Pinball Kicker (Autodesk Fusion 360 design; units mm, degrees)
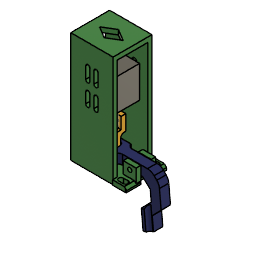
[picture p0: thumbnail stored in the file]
sketch "Solenoid Assy" plane through (0, 0, 0) normal (0, 0, 1) x axis (1, 0, 0)
  line L1 (18.001, -16.536) -> (18.0004, 16.543)
  line L2 (-17.999, -16.5011) -> (-17.9996, 16.5424)
  line L3 (-17.9995, 13.0183) -> (18.0005, 13.0189)
  line L4 (15.0006, -16.5331) -> (15, 16.543)
  line L5 (18.0004, 16.543) -> (-17.9996, 16.5424)
  line L6 (18.001, -16.536) -> (-17.999, -16.5011)
  line L7 (18, -12.9962) -> (-17.999, -12.999)
  line L8 (-14.9977, 16.5424) -> (-14.9977, 16.5374)
  line L9 (-17.999, -16.5011) -> (-17.999, -16.5011)
  line L10 (18.001, -12.9962) -> (18, -12.9962)
  line L11 (-14.9983, -16.504) -> (-14.9977, 16.5374)
  line L12 (-17.9995, -16.9987) -> (-17.999, -16.5011)
  line L13 (-17.9996, 16.5424) -> (-17.9993, 16.9967)
  line L14 (-15.5, -9.1) -> (-12.5, -9.1)
  line L15 (-15.5, -4.9) -> (-12.5, -4.9)
  line L16 (-15.5, 4.9) -> (-12.5, 4.9)
  line L17 (-15.5, 9.1) -> (-12.5, 9.1)
  arc A1 centre (-12.5, -7) radius 2.1 clockwise from (-12.5, -4.9) to (-12.5011, -9.1)
  arc A2 centre (-15.5, -7) radius 2.1 clockwise from (-15, -4.9604) to (-14.9981, -4.9609)
  arc A3 centre (-15.5, -7) radius 2.1 clockwise from (-15.4986, -9.1) to (-15.5, -4.9)
  arc A4 centre (-15.5, -7) radius 2.1 clockwise from (-14.9982, -9.0392) to (-15, -9.0396)
  arc A5 centre (-12.5, 7) radius 2.1 clockwise from (-12.5007, 9.1) to (-12.5, 4.9)
  arc A6 centre (-15.5, 7) radius 2.1 clockwise from (-15.5, 4.9) to (-15.4993, 9.1)
  arc A7 centre (-15.5, 7) radius 2.1 clockwise from (-14.9979, 4.9609) to (-15, 4.9604)
  arc A8 centre (-15.5, 7) radius 2.1 clockwise from (-15, 9.0396) to (-14.9979, 9.0391)
  point P13 (15.0006, -16.5331)
  point P12 (-14.9983, -16.504)
  point P10 (-17.999, -12.999)
  point P8 (-17.9995, 13.0183)
  point P4 (18.001, -12.9962)
  point P5 (-14.9977, 16.5424)
  point P15 (18.0005, 13.0189)
  point P16 (15, 16.543)
  point P23 (-12.5, -9.1)
  point P24 (-15.5, -9.1)
  point P26 (-15.5, -4.9)
  point P27 (-12.5011, -9.1)
  point P28 (-14.9982, -9.0392)
  point P29 (-14.9981, -4.9609)
  point P32 (-15.4986, -9.1)
  point P37 (-12.5, 9.1)
  point P38 (-15.5, 9.1)
  point P40 (-12.5007, 9.1)
  point P42 (-15.4993, 9.1)
  point P44 (-14.9979, 4.9609)
  point P45 (-14.9979, 9.0391)
  coincident P13 L6
  coincident P12 L6
  coincident P10 L2
  coincident P8 L2
  perpendicular L2 L9
  coincident P4 L1
  perpendicular L5 L8
  coincident P5 L5
  perpendicular L1 L3
  coincident L1 P15
  perpendicular L4 L5
  coincident L5 P16
  perpendicular L6 L12
  coincident P23 A1
  coincident P24 A2
  tangent L14 A2
  coincident P26 A2
  tangent L15 A2
  coincident L14 P27
  coincident L11 P28
  coincident L11 P29
  concentric A2 A3
  coincident L14 P32
  concentric A3 A4
  tangent L16 A7
  coincident P37 A5
  coincident P38 A7
  tangent L17 A7
  coincident L17 P40
  coincident L17 P42
  concentric A6 A7
  coincident L11 P44
  coincident L11 P45
  concentric A7 A8
  dimension "d157" diameter A7 = 4.2
  dimension "d159" diameter A5 = 4.2
extrude "Extrude1" new body sketch "Solenoid Assy" profile of L1 L2 L3 L4 L5 L6 L7 L8 L9 L10 L11 along normal blind 90 bodies "Base Assembly"
extrude "Extrude2" add sketch "Solenoid Assy" profile of L1 L2 L3 L4 L7 L10 L11 A4 A8 A5 A1 L14 L15 L16 L17 along normal blind 4
sketch "Solenoid Assy Rear" plane through (0, 0, 90) normal (0, 0, 1) x axis (-1, 0, 0)
  line L1 (17.9995, -13.0183) -> (17.9996, -16.5424)
  line L2 (-18.0004, -16.543) -> (-18.0005, -13.0189)
  line L3 (17.9996, -16.5424) -> (-18.0004, -16.543)
  line L4 (-18.0004, -16.543) -> (17.9996, -16.5424)
  line L5 (-18.001, 16.536) -> (-18.0004, -16.543)
  line L6 (17.999, 16.5011) -> (-18.001, 16.536)
  line L7 (17.9996, -16.5424) -> (17.999, 16.5011)
  line L8 (0, 6) -> (10, 0)
  line L9 (-10, 0) -> (0, 6)
  line L10 (0, -6) -> (-10, 0)
  line L11 (10, 0) -> (0, -6)
  point P2 (17.9996, -16.5424)
  point P6 (17.9996, -16.5424)
  point P5 (-18.0004, -16.543)
  point P7 (-18.0004, -16.543)
  point P9 (-18.0004, -16.543)
  point P8 (-18.001, 16.536)
  point P10 (-18.001, 16.536)
  point P11 (17.999, 16.5011)
  point P12 (17.999, 16.5011)
  coincident P2 P6
  coincident P5 P7
  coincident P5 P9
  coincident P8 P10
  coincident P11 P12
  parallel L8 L10
  parallel L9 L11
extrude "Extrude3" add sketch "Solenoid Assy Rear" along normal blind 4
sketch "37mm Solenoid Base View" plane through (18.0007, 0.0003, 0) normal (1, 0, 0) x axis (0, 1, 0)
  line L1 (13.0186, 4) -> (13.0186, 90)
  line L2 (-12.9966, 90) -> (-12.9966, 4)
  line L3 (13.0186, 90) -> (-12.9966, 90)
  line L4 (16.5427, 94) -> (16.5427, 0)
  line L5 (-16.5363, 94) -> (16.5427, 94)
  line L6 (-16.5363, 0) -> (-16.5363, 94)
  line L7 (16.5427, 0) -> (-16.5363, 0)
  line L8 (4, 10) -> (-4, 10)
  line L9 (4, 31) -> (4, 10)
  line L10 (-4, 31) -> (4, 31)
  line L11 (-4, 10) -> (-4, 31)
  line L12 (-4, 13) -> (4, 13)
  line L13 (-4, 16) -> (4, 16)
  line L14 (-12.9966, 31) -> (13.0186, 31)
  line L15 (-12.9966, 68) -> (-12.9966, 31)
  line L16 (13.0186, 68) -> (-12.9966, 68)
  line L17 (13.0186, 31) -> (13.0186, 68)
  line L18 (-12.9966, 4) -> (13.0186, 4)
  point P16 (4, 13)
  point P17 (-4, 13)
  point P18 (4, 16)
  point P19 (-4, 16)
  point P20 (13.0186, 31)
  point P21 (-12.9966, 31)
  point P22 (-12.9966, 68)
  point P23 (13.0186, 68)
  horizontal L8
  perpendicular L8 L9
  perpendicular L9 L10
  perpendicular L8 L11
  coincident L9 P16
  coincident L11 P17
  perpendicular L11 L12
  coincident L9 P18
  perpendicular L9 L13
  coincident L11 P19
  coincident L1 P20
  perpendicular L1 L14
  coincident L2 P21
  coincident L2 P22
  coincident L1 P23
  perpendicular L1 L16
sketch "27mm Solenoid BAse View" plane through (18.0007, 0.0003, 0) normal (1, 0, 0) x axis (0, 1, 0)
  line L1 (4, 31) -> (4, 10)
  line L2 (4, 10) -> (-4, 10)
  line L3 (4, 29) -> (4, 10)
  line L4 (-4, 29) -> (4, 29)
  line L5 (-4, 29) -> (-4, 10)
  line L6 (-4, 13) -> (4, 13)
  line L7 (-4, 16) -> (4, 16)
  line L8 (-12.9986, 90) -> (-12.9986, 4)
  line L9 (-12.9966, 90) -> (-12.9966, 4)
  line L10 (-12.9966, 56.0771) -> (-12.9986, 29)
  line L11 (13.0186, 31) -> (13.0186, 68)
  line L12 (13.0186, 56.0751) -> (-12.9966, 56.0771)
  line L13 (13, 29) -> (13.0186, 56.0751)
  line L14 (-12.9986, 29) -> (13, 29)
  point P2 (-4, 10)
  point P6 (-4, 10)
  point P3 (4, 10)
  point P7 (4, 10)
  point P9 (-4, 10)
  point P11 (4, 13)
  point P13 (4, 13)
  point P12 (-4, 13)
  point P14 (-4, 13)
  point P15 (4, 16)
  point P17 (4, 16)
  point P16 (-4, 16)
  point P18 (-4, 16)
  point P24 (-12.9986, 29)
  point P25 (-12.9966, 56.0771)
  point P28 (13.0186, 56.0751)
  coincident P2 P6
  coincident P3 P7
  perpendicular L2 L3
  perpendicular L1 L4
  coincident P2 P9
  perpendicular L4 L5
  coincident P11 P13
  coincident P12 P14
  coincident P15 P17
  coincident P16 P18
  coincident L8 P24
  coincident L9 P25
  coincident L11 P28
  perpendicular L10 L12
  perpendicular L9 L14
extrude "Extrude4" new body sketch "27mm Solenoid BAse View" profile of L4 L9 L12 L13 L14 blind -22 from offset -7 bodies "27mm Solenoid"
extrude "Extrude5" add sketch "27mm Solenoid BAse View" profile of L1 L2 L3 L4 L5 L6 L7 blind -8 from offset -14
fillet "Fillet1" radius 3
extrude "Extrude6" new body sketch "37mm Solenoid Base View" profile of L1 L2 L10 L14 L15 L16 L17 blind -22 from offset -7 bodies "37mm Solenoid"
extrude "Extrude7" add sketch "37mm Solenoid Base View" profile of L8 L9 L10 L11 L12 L13 L14 blind -8 from offset -14
fillet "Fillet2" radius 3
sketch "37mm drill" plane through (0.0002, -12.9966, 0) normal (0, -1, 0) x axis (1, 0, 0)
  line L1 (11.0007, 68) -> (11.0007, 31)
  line L2 (-10.9993, 68) -> (11.0007, 68)
  line L3 (-10.9993, 31) -> (-10.9993, 68)
  line L4 (11.0007, 31) -> (-10.9993, 31)
  line L5 (11.0007, 58.0024) -> (11.0007, 38.0024)
  line L6 (-10.9993, 58.0024) -> (-10.9993, 38.0024)
  line L7 (5.2499, 65.9518) -> (5.2499, 76.0213)
  line L8 (1.7507, 66.0063) -> (1.7507, 76.0481)
  line L9 (-1.7501, 65.9518) -> (-1.7501, 76.0213)
  line L10 (-5.2493, 66.0062) -> (-5.2499, 76.0153)
  line L11 (5.2499, 47.9519) -> (5.2499, 57.0213)
  line L12 (1.7507, 48.0062) -> (1.7502, 57.024)
  line L13 (-1.7501, 47.9518) -> (-1.7501, 57.0213)
  line L14 (-5.2493, 48.0063) -> (-5.2493, 57.0497)
  arc A1 centre (3.5007, 73.0024) radius 1.75 clockwise from (5.2499, 73.0569) to (5.2499, 72.9478)
  arc A2 centre (3.5, 76) radius 1.75 clockwise from (1.7507, 75.9519) to (5.2499, 75.9787)
  arc A3 centre (3.5007, 66.0063) radius 1.75 clockwise from (5.2499, 66.0607) to (1.7507, 66.0063)
  arc A4 centre (-3.4993, 66.0063) radius 1.75 clockwise from (-1.7501, 66.0608) to (-5.2493, 66.0062)
  arc A5 centre (-3.5, 76) radius 1.75 clockwise from (-5.2499, 75.9845) to (-1.7501, 75.9787)
  arc A6 centre (3.5, 57) radius 1.75 clockwise from (1.7502, 56.9758) to (5.2499, 56.9787)
  arc A7 centre (3.5007, 48.0063) radius 1.75 clockwise from (5.2499, 48.0607) to (1.7507, 48.0062)
  arc A8 centre (-3.5, 57) radius 1.75 clockwise from (-5.2493, 56.9503) to (-1.7501, 56.9787)
  arc A9 centre (-3.4993, 48.0063) radius 1.75 clockwise from (-1.7501, 48.0608) to (-5.2493, 48.0063)
  point P6 (11.0007, 38.0024)
  point P8 (-10.9993, 58.0024)
  point P9 (-10.9993, 38.0024)
  point P13 (5.2499, 76.0213)
  point P14 (5.2499, 65.9518)
  point P15 (1.7507, 76.0481)
  point P19 (1.7507, 75.9519)
  point P20 (5.2499, 66.0607)
  point P22 (-1.7501, 76.0213)
  point P23 (-1.7501, 65.9518)
  point P30 (-5.2499, 76.0153)
  point P27 (-1.7501, 75.9787)
  point P26 (-5.2499, 75.9845)
  point P24 (-1.7501, 66.0608)
  point P31 (5.2499, 57.0213)
  point P32 (5.2499, 47.9519)
  point P48 (1.7502, 57.024)
  point P44 (1.7502, 56.9758)
  point P42 (5.2499, 48.0607)
  point P40 (-1.7501, 57.0213)
  point P35 (-1.7501, 47.9518)
  point P34 (-5.2493, 57.0497)
  point P39 (-1.7501, 56.9787)
  point P37 (-5.2493, 56.9503)
  point P38 (-1.7501, 48.0608)
  coincident L1 P6
  coincident L3 P8
  coincident L3 P9
  coincident P13 A2
  coincident P14 A3
  coincident P15 A2
  tangent L8 A3
  coincident L8 P19
  coincident L7 P20
  coincident P22 A5
  coincident P23 A4
  coincident P30 A5
  tangent A4 L10
  coincident P27 L9
  coincident P26 L10
  coincident P24 L9
  coincident P31 A6
  coincident P32 A7
  coincident P48 A6
  tangent L12 A7
  coincident P44 L12
  coincident P42 L11
  coincident P40 A8
  coincident P35 A9
  coincident P34 A8
  tangent L14 A9
  coincident P39 L13
  coincident P37 L14
  coincident P38 L13
extrude "Extrude8" cut sketch "37mm drill" profile of A2 A3 L7 L8 A4 L9 L10 A5 L11 L12 A6 A7 L13 A8 L14 A9 along normal blind 10
sketch "27mm drill" plane through (-0.0002, 12.9801, -0.0089) normal (0, 1, -0.0007) x axis (-1, 0, 0)
  line L1 (-11.0007, 29.0089) -> (-11.0007, 56.084)
  line L2 (10.9993, 29.0089) -> (-11.0007, 29.0089)
  line L3 (10.9993, 56.084) -> (10.9993, 29.0089)
  line L4 (10.9993, 29.0089) -> (-11.0007, 29.0089)
  line L5 (8.45, 56) -> (8.45, 42)
  line L6 (4.35, 56) -> (4.35, 42)
  line L7 (-4.35, 71) -> (-4.35, 57)
  line L8 (-8.45, 71) -> (-8.45, 57)
  arc A1 centre (6.4, 56) radius 2.05 clockwise from (4.35, 56) to (8.45, 56)
  arc A2 centre (6.4, 42) radius 2.05 clockwise from (8.45, 42) to (4.35, 42)
  arc A3 centre (-6.4, 71) radius 2.05 clockwise from (-8.45, 71) to (-4.35, 71)
  arc A4 centre (-6.4, 57) radius 2.05 clockwise from (-4.35, 57) to (-8.45, 57)
  point P3 (-11.0007, 29.0089)
  point P6 (-11.0007, 29.0089)
  point P4 (10.9993, 29.0089)
  point P7 (10.9993, 29.0089)
  coincident P3 P6
  coincident P4 P7
  vertical L5
  vertical L6
  dimension "d166" diameter A1 = 4.1
  dimension "d167" diameter A2 = 4.1
  dimension "d168" diameter A3 = 4.1
  dimension "d169" diameter A4 = 4.1
extrude "Extrude9" cut sketch "27mm drill" profile of A1 A2 L5 L6 A3 A4 L7 L8 along normal blind 10 and against normal blind 1
sketch "Board Level Plane" plane through (0, 0, 0) normal (0, 0, -1) x axis (1, 0, 0)
  line L1 (-17.9996, -16.5424) -> (-17.999, 16.5011)
  line L2 (18.001, 16.536) -> (18.0004, -16.543)
  line L3 (27.5, 4) -> (37.5, 4)
  line L4 (27.5, -4) -> (37.5, -4)
  line L5 (38.5, 4) -> (38.5, -4)
  line L6 (37.5, 4) -> (38.5, 4)
  line L7 (38.5, -4) -> (37.5, -4)
  line L8 (27.5, -4) -> (27.5, 4)
  line L9 (31.1, -4) -> (31.1, 4)
  line L10 (34.9, 4) -> (34.9, -4)
  line L11 (-5.5, -4) -> (-5.5, 4)
  line L12 (-5.5, -4) -> (27.5, -4)
  line L13 (27.5, 4) -> (-5.5, 4)
  line L14 (1.9, 4) -> (1.9, -4)
  line L15 (-1.9, -4) -> (-1.9, 4)
  line L16 (8, 4) -> (8, -4)
  line L17 (18.0004, -16.543) -> (-17.9996, -16.5424)
  line L18 (-17.999, 16.5011) -> (18.001, 16.536)
  line L19 (-17.999, 16.5011) -> (-17.999, 16.5011)
  line L20 (-12.5, -4.9) -> (-15.5, -4.9)
  line L21 (-15.5, 4.9) -> (-12.5, 4.9)
  line L22 (-15.4993, -9.1) -> (-12.5007, -9.1)
  line L23 (-12.5011, 9.1) -> (-15.4986, 9.1)
  arc A1 centre (-12.5, 7) radius 2.1 clockwise from (-12.5011, 9.1) to (-12.5, 4.9)
  arc A2 centre (-12.5, -7) radius 2.1 clockwise from (-12.5, -4.9) to (-12.5007, -9.1)
  arc A3 centre (-15.5, -7) radius 2.1 clockwise from (-15.4993, -9.1) to (-15.5, -4.9)
  arc A4 centre (-15.5, 7) radius 2.1 clockwise from (-15.5, 4.9) to (-15.4986, 9.1)
  point P22 (8, -4)
  point P23 (8, 4)
  perpendicular L5 L6
  perpendicular L4 L8
  perpendicular L8 L12
  perpendicular L8 L13
  coincident L12 P22
  coincident L13 P23
  perpendicular L13 L16
sketch "Solenoid Coupling" plane through (0, 0, 0) normal (0, 0, -1) x axis (1, 0, 0)
  line L1 (4.5975, -4.2033) -> (-4.5002, -4.1951)
  line L2 (-4.5001, 4.2001) -> (-4.5002, -4.1951)
  line L3 (-4.5002, -4.1951) -> (-4.5029, -7.1959)
  line L4 (4.5075, 7.1999) -> (-4.5001, 7.2001)
  line L5 (-4.5029, -7.1959) -> (4.5948, -7.2041)
  line L6 (4.5948, -7.2041) -> (4.5975, -4.2033)
  line L7 (-4.5001, 7.2001) -> (-4.5001, 4.2001)
  line L8 (1.9, 7.2) -> (1.9, 4.2)
  line L9 (-1.9, 7.2) -> (-1.9, 4.2001)
  line L10 (1.8969, -7.2017) -> (1.8996, -4.2009)
  line L11 (-1.9031, -7.1983) -> (-1.9004, -4.1974)
  line L12 (9.5948, -7.2041) -> (4.5948, -7.2041)
  line L13 (4.6051, 4.1919) -> (-4.5001, 4.2001)
  line L14 (9.6078, 7.1999) -> (9.5948, -7.2041)
  line L15 (-4.5001, 7.2001) -> (9.6078, 7.1999)
  line L16 (4.5975, -4.2002) -> (4.5948, -7.2041)
  line L17 (4.6078, 7.1999) -> (4.6051, 4.1919)
  line L18 (1.9, 4.1943) -> (1.9, 4.2)
  line L19 (-1.9, 4.1978) -> (-1.9, 4.2001)
  line L20 (4.6078, 7.2) -> (4.6078, 7.1999)
  arc A1 centre (0, 0) radius 6.2273 clockwise from (4.6051, 4.1919) to (4.596, -4.2019)
  point P10 (1.9, 7.2)
  point P11 (-1.9, 7.2)
  point P12 (1.8969, -7.2017)
  point P13 (-1.9031, -7.1983)
  point P14 (-1.9004, -4.1974)
  point P15 (1.8996, -4.2009)
  point P20 (4.6051, 4.1919)
  point P2 (0, 0)
  point P23 (0, 0)
  point P25 (4.5975, -4.2002)
  point P26 (-1.9, 4.1978)
  point P27 (1.9, 4.1943)
  point P28 (4.6078, 7.2)
  perpendicular L4 L7
  perpendicular L3 L5
  perpendicular L1 L3
  perpendicular L5 L6
  coincident L4 P10
  perpendicular L4 L8
  coincident L4 P11
  perpendicular L4 L9
  coincident L5 P12
  perpendicular L5 L10
  coincident L5 P13
  perpendicular L5 L11
  coincident L1 P14
  coincident L1 P15
  horizontal L12
  coincident P20 L16
  coincident P2 P23
  coincident A1 P25
  collinear L16 L17
  perpendicular L13 L18
  perpendicular L13 L19
  coincident L13 P26
  coincident L13 P27
  coincident L15 P28
sketch "Kicker Lever Pivot" plane through (0, 0, 0) normal (0, 0, -1) x axis (1, 0, 0)
  line L1 (27.5, -4) -> (27.5, 4)
  line L2 (18.5, 4.4) -> (29.8333, 4.4)
  line L3 (18.5, -4.4) -> (29.5, -4.4)
  line L4 (25.9, -8.2) -> (25.9, -4.4)
  line L5 (22.1, -8.2) -> (22.1, -4.4)
  line L6 (18.5, -8.2) -> (29.5, -8.2)
  line L7 (29.5, -8.2) -> (29.5, -4.4)
  line L8 (18.5, -4.4) -> (18.5, -8.2)
  line L9 (18.5, 4.4) -> (29.5, 4.4)
  line L10 (22.1, 4.4) -> (22.1, 8.4)
  line L11 (29.5, 4.4) -> (29.5, 8.4)
  line L12 (18.5, 8.4) -> (29.5, 8.4)
  line L13 (25.9, 4.2) -> (25.9, 8.4)
  line L14 (18.5, 8.4) -> (18.5, 4.4)
  line L15 (30, -17) -> (29, -17)
  line L16 (29, 17) -> (30, 17)
  line L17 (18.001, 16.536) -> (18.0004, -16.543)
  line L18 (18.001, 17.0002) -> (29, 17)
  line L19 (18.0004, -16.9998) -> (29, -17)
  line L20 (25.9, 4.2) -> (25.9, -4.4)
  line L21 (30, -4.5) -> (29.5, -4.4)
  line L22 (30, 4.5) -> (29.8333, 4.4)
  line L23 (30, 4.4) -> (29.8333, 4.4)
  line L24 (30, -4.4) -> (29.5, -4.4)
  line L25 (26.5, -4.3) -> (26.625, -4.4)
  line L26 (26.5, 4.3) -> (26.5, -4.3)
  line L27 (26.625, 4.4) -> (26.5, 4.3)
  line L28 (30, -4.4) -> (30, -17)
  line L29 (30, 17) -> (30, 4.4)
  line L30 (18.001, 17.0002) -> (18.0004, -16.9998)
  line L31 (21.5001, 15.3) -> (25.4745, 15.2998)
  line L32 (21.5001, 11.1) -> (25.4745, 11.1002)
  line L33 (21.5001, -11.1) -> (25.4745, -11.1002)
  line L34 (21.5001, -15.3) -> (25.4745, -15.2998)
  arc A1 centre (21.5, -13.2) radius 2.1 clockwise from (21.5001, -15.3) to (21.5001, -11.1)
  arc A2 centre (25.5, -13.2) radius 2.1 clockwise from (25.4745, -11.1002) to (25.4745, -15.2998)
  arc A3 centre (25.5, 13.2) radius 2.1 clockwise from (25.4745, 15.2998) to (25.4745, 11.1002)
  arc A4 centre (21.5, 13.2) radius 2.1 clockwise from (21.5001, 11.1) to (21.5001, 15.3)
  point P11 (25.9, -4.4)
  point P12 (22.1, -4.4)
  point P19 (25.9, 8.4)
  point P17 (22.1, 8.4)
  point P30 (18.001, 17.0002)
  point P31 (18.0004, -16.9998)
  point P32 (30, -4.5)
  point P33 (30, 4.5)
  point P34 (22.1, 4.4)
  point P35 (30, 4.4)
  point P37 (26.625, -4.4)
  point P40 (26.625, 4.4)
  perpendicular L1 L2
  perpendicular L3 L4
  vertical L4
  vertical L5
  coincident L3 P11
  coincident L3 P12
  perpendicular L6 L7
  perpendicular L3 L8
  perpendicular L12 L13
  vertical L13
  vertical L10
  coincident P19 L12
  coincident P17 L12
  perpendicular L9 L11
  perpendicular L12 L14
  perpendicular L15 L28
  coincident L17 P30
  perpendicular L17 L18
  coincident L17 P31
  perpendicular L17 L19
  perpendicular L9 L20
  coincident P32 L28
  coincident P33 L28
  coincident L2 P34
  coincident P35 L28
  perpendicular L23 L28
  perpendicular L24 L28
  coincident L3 P37
  perpendicular L9 L26
  coincident L2 P40
  collinear L28 L29
  tangent L31 A4
  tangent L32 A4
  tangent L33 A1
  tangent L34 A1
extrude "Extrude11" new body sketch "Solenoid Coupling" profile of L1 L3 L4 L5 L6 L7 L8 L9 L10 L11 L12 L17 L13 L14 L15 A1 L18 L19 L20 blind -8 from offset -6 bodies "Kicker_Lever"
extrude "Extrude13" add sketch "Board Level Plane" profile of L2 L3 L4 L5 L6 L7 L8 L9 L10 L12 L13 L16 blind -8 from offset -6
extrude "Extrude14" new body sketch "Kicker Lever Pivot" + "Solenoid Assy" profile of S2:L1 S2:L2 S2:L3 S2:L4 S2:L7 S2:L10 S2:L11 S1:L2 S1:L3 S1:L4 S1:L5 S1:L6 S1:L7 S1:L8 S1:L9 S1:L10 S1:L11 S1:L12 S1:L13 S1:L14 S1:A4 S1:A1 S1:L15 S1:L29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 blind -4
extrude "Extrude15" new body sketch "Kicker Lever Pivot" profile of L2 L3 L4 L5 L6 L7 L8 L9 L10 L11 L12 L13 L14 against normal blind 14
sketch "Kicker Arm Axle" plane through (0.0001, -7.2, 0) normal (0, -1, 0) x axis (1, 0, 0)
  line L1 (9.6078, 6) -> (-4.5001, 6)
  line L2 (9.6078, 14) -> (9.6078, 6)
  line L3 (-4.5001, 14) -> (9.6078, 14)
  line L4 (-4.5001, 6) -> (-4.5001, 14)
  circle C1 centre (0, 9.8804) radius 1.75
extrude "Extrude16" cut sketch "Kicker Arm Axle" profile of C1 against normal blind 15
combine "Combine1"
sketch "Kicker Pivot Axle" plane through (0, -8.4, 0) normal (0, -1, 0) x axis (1, 0, 0)
  line L1 (29.5, 14) -> (29.5, 4)
  line L2 (18.5, 14) -> (29.5, 14)
  line L3 (18.5, 4) -> (18.5, 14)
  line L4 (29.5, 4) -> (18.5, 4)
  circle C1 centre (24, 10) radius 1.75
extrude "Extrude17" cut sketch "Kicker Pivot Axle" profile of C1 against normal blind 20
move "Move1"
move "Move2"
sketch "Kicker Coupling" plane through (-0.0038, 4.1992, 0) normal (0.0009, -1, 0) x axis (1, 0.0009, 0)
  line L1 (4.6013, 6) -> (-4.4964, 6)
  line L2 (4.6013, 14) -> (4.6013, 6)
  line L3 (-4.4964, 14) -> (4.6013, 14)
  line L4 (-4.4964, 6) -> (-4.4964, 14)
  line L5 (4, 6) -> (-3.9964, 6)
  line L6 (4, 33) -> (4, 6)
  line L7 (-3.9964, 33) -> (4, 33)
  line L8 (-1.0028, 25) -> (0.9972, 25)
  line L9 (-3.9964, 23) -> (4, 23)
  line L10 (-3.9964, 20) -> (4, 20)
  line L11 (-3.9964, 6) -> (-3.9964, 33)
  closed curve K1 centre (0.0038, 9.8804)
  circle C1 centre (-0.0028, 28.5) radius 1.75
  point P7 (4, 6)
  point P15 (-3.9964, 23)
  point P16 (-3.9964, 20)
  point P17 (4, 20)
  point P18 (4, 23)
  coincident L1 P7
  perpendicular L3 L6
  coincident L11 P15
  coincident L11 P16
  coincident L6 P17
  coincident L6 P18
extrude "Extrude18" new body sketch "Kicker Coupling" profile of K1 L1 L3 L5 L6 L9 L10 L11 blind 7.8 from offset 0.3 bodies "Kicker Coupling"
extrude "Extrude19" new body sketch "Kicker Coupling" profile of L6 L7 C1 L9 L10 L11 blind -4 from offset -0.1
extrude "Extrude20" new body sketch "Kicker Coupling" profile of L6 L7 C1 L9 L10 L11 blind 4 from offset 8.4
extrude "Extrude21" add sketch "Kicker Coupling" profile of L6 L9 L10 L11 along normal blind 9 and against normal blind 1
fillet "Fillet3" radius 3
fillet "Fillet4" radius 3
extrude "Extrude22" cut sketch "Kicker Coupling" profile of C1 along normal blind 22 and against normal blind 10
sketch "Kicker Arm" plane through (0, -4, 0) normal (0, -1, 0) x axis (1, 0, 0)
  line L1 (9.6049, 6) -> (9.6049, 14)
  line L2 (38.5, 6) -> (9.6049, 6)
  line L3 (38.5, 14) -> (38.5, 6)
  line L4 (9.6049, 14) -> (38.5, 14)
  line L5 (35.637, -22.4795) -> (34.6113, -11.4021)
  line L6 (28, 6) -> (28, 14)
  line L7 (30.5, 6) -> (28, 6)
  line L8 (28, 14) -> (38, 14)
  line L9 (37, 0) -> (31.0556, 0)
  line L10 (46.0181, -7.7957) -> (44.6122, 7.3878)
  line L11 (44.6122, 7.3878) -> (38, 14)
  line L12 (38.5, 14) -> (38, 14)
  line L13 (30.5, 6) -> (37, 0)
  line L14 (33.1582, -22.709) -> (32.1326, -11.6316)
  line L15 (38.5, 8.6) -> (38, 14)
  line L16 (37.558, -6.0264) -> (37, 0)
  line L17 (39.0522, -22.1632) -> (38.4462, -15.6186)
  line L18 (33.6192, -27.6877) -> (33.1582, -22.709)
  line L19 (36.098, -27.4582) -> (35.637, -22.4795)
  line L20 (39.5131, -27.1419) -> (39.0522, -22.1632)
  line L21 (39.5131, -27.1419) -> (33.6192, -27.6877)
  line L22 (34.6113, -11.4021) -> (32.1326, -11.6316)
  line L23 (37.558, -6.0264) -> (32.1326, -11.6316)
  line L24 (43.8716, -10.0134) -> (38.4462, -15.6186)
  line L25 (46.0181, -7.7957) -> (43.8716, -10.0134)
  line L26 (37.1892, -2.0434) -> (37.558, -6.0264)
  circle C1 centre (24, 10) radius 1.75
  point P20 (38.5, 8.6)
  perpendicular L4 L6
  horizontal L9
  horizontal L12
  coincident L3 P20
  collinear L16 L17
  perpendicular L20 L21
  parallel L24 L25
  parallel L16 L26
extrude "Extrude23" add sketch "Kicker Arm" profile of L2 L3 L14 L5 L17 L10 L11 L13 against normal blind 8
extrude "Extrude24" add sketch "Kicker Arm" profile of L14 L5 L18 L19 L21 L22 along normal blind 3 and against normal blind 11
chamfer "Chamfer4" distance 2
fillet "Fillet7" radius 8
chamfer "Chamfer5" distance 10
fillet "Fillet8" radius 2
chamfer "Chamfer6" distance 2
chamfer "Chamfer7" distance 2
fillet "Fillet9" radius 2
fillet "Fillet10" radius 2
fillet "Fillet11" radius 0.6
fillet "Fillet12" radius 0.5
fillet "Fillet13" radius 8
fillet "Fillet18" radius 3
fillet "Fillet19" radius 8
chamfer "Chamfer16" distance 3 distance 3
fillet "Fillet20" radius 4
extrude "Extrude27" cut sketch "Solenoid Assy" profile of L11 A4 A8 A5 A1 L14 L15 L16 L17 along normal blind 5
combine "Combine2"
combine "Combine3"
chamfer "Chamfer17" distance 3.5
sketch "Kicker Arm 12mm Deck" plane through (0, -4, 0) normal (0, -1, 0) x axis (1, 0, 0)
  line L1 (38.5, 14) -> (38, 14)
  line L2 (37, 0) -> (31.0556, 0)
  line L3 (35.9136, -25.4667) -> (34.8879, -14.3893)
  line L4 (39.7897, -30.1292) -> (33.8958, -30.6749)
  line L5 (30.5, 6) -> (37, 0)
  line L6 (9.6049, 6) -> (9.6049, 14)
  line L7 (36.3746, -30.4454) -> (35.9136, -25.4667)
  line L8 (39.3287, -25.1505) -> (38.7228, -18.6058)
  line L9 (28, 14) -> (38, 14)
  line L10 (37.8346, -9.0136) -> (32.4091, -14.6188)
  line L11 (33.4348, -25.6962) -> (32.4091, -14.6188)
  line L12 (39.7897, -30.1292) -> (39.3287, -25.1505)
  line L13 (38.5, 8.6) -> (38, 14)
  line L14 (34.8879, -14.3893) -> (32.4091, -14.6188)
  line L15 (33.8958, -30.6749) -> (33.4348, -25.6962)
  line L16 (46.2947, -10.783) -> (44.1482, -13.0006)
  line L17 (28, 6) -> (28, 14)
  line L18 (44.6122, 7.3878) -> (38, 14)
  line L19 (37.1892, -2.0434) -> (37.8346, -9.0136)
  line L20 (30.5, 6) -> (28, 6)
  line L21 (38.5, 6) -> (9.6049, 6)
  line L22 (38.5, 14) -> (38.5, 6)
  line L23 (9.6049, 14) -> (38.5, 14)
  line L24 (46.2947, -10.783) -> (44.6122, 7.3878)
  line L25 (37.8346, -9.0136) -> (37, 0)
  line L26 (44.1482, -13.0006) -> (38.7228, -18.6058)
  line L27 (34.1724, -33.6621) -> (33.8958, -30.6749)
  circle C1 centre (24, 10) radius 1.75
  point P23 (38.5, 8.6)
  point P8 (33.8958, -30.6749)
  point P34 (34.1724, -33.6621)
  perpendicular L17 L23
  horizontal L2
  horizontal L1
  coincident P23 L22
  collinear L8 L25
  perpendicular L4 L12
  parallel L16 L26
  parallel L19 L25
  perpendicular L4 L27
  dimension "d171" distance P8 P34 = 3
extrude "Extrude28" new body sketch "Kicker Arm 12mm Deck" profile of C1 L3 L4 L5 L6 L7 L8 L9 L10 L11 L12 L13 L14 L15 L16 L17 L18 L19 L20 L21 L22 L23 L24 L25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 against normal blind 8 bodies "Kicker Lever 12mm deck"
extrude "Extrude29" add sketch "Kicker Arm 12mm Deck" profile of L3 L4 L7 L11 L14 L15 along normal blind 3 and against normal blind 11
extrude "Extrude30" add sketch "Solenoid Coupling" profile of L1 L3 L4 L5 L6 L7 L8 L9 L10 L11 L12 L17 L13 L14 L15 A1 L18 L19 L20 blind -8 from offset -6
extrude "Extrude31" cut sketch "Kicker Arm Axle" profile of C1 against normal blind 40
extrude "Extrude32" add sketch "Board Level Plane" profile of L2 L12 L13 L16 blind -8 from offset -6
fillet "Fillet21" radius 4
fillet "Fillet22" radius 4
fillet "Fillet23" radius 8
fillet "Fillet24" radius 3
fillet "Fillet25" radius 3
chamfer "Chamfer18" distance 3
chamfer "Chamfer19" distance 3
named bodies: "Base Assembly", "27mm Solenoid", "37mm Solenoid", "Kicker_Lever", "Kicker Coupling", "Kicker Lever 12mm deck"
